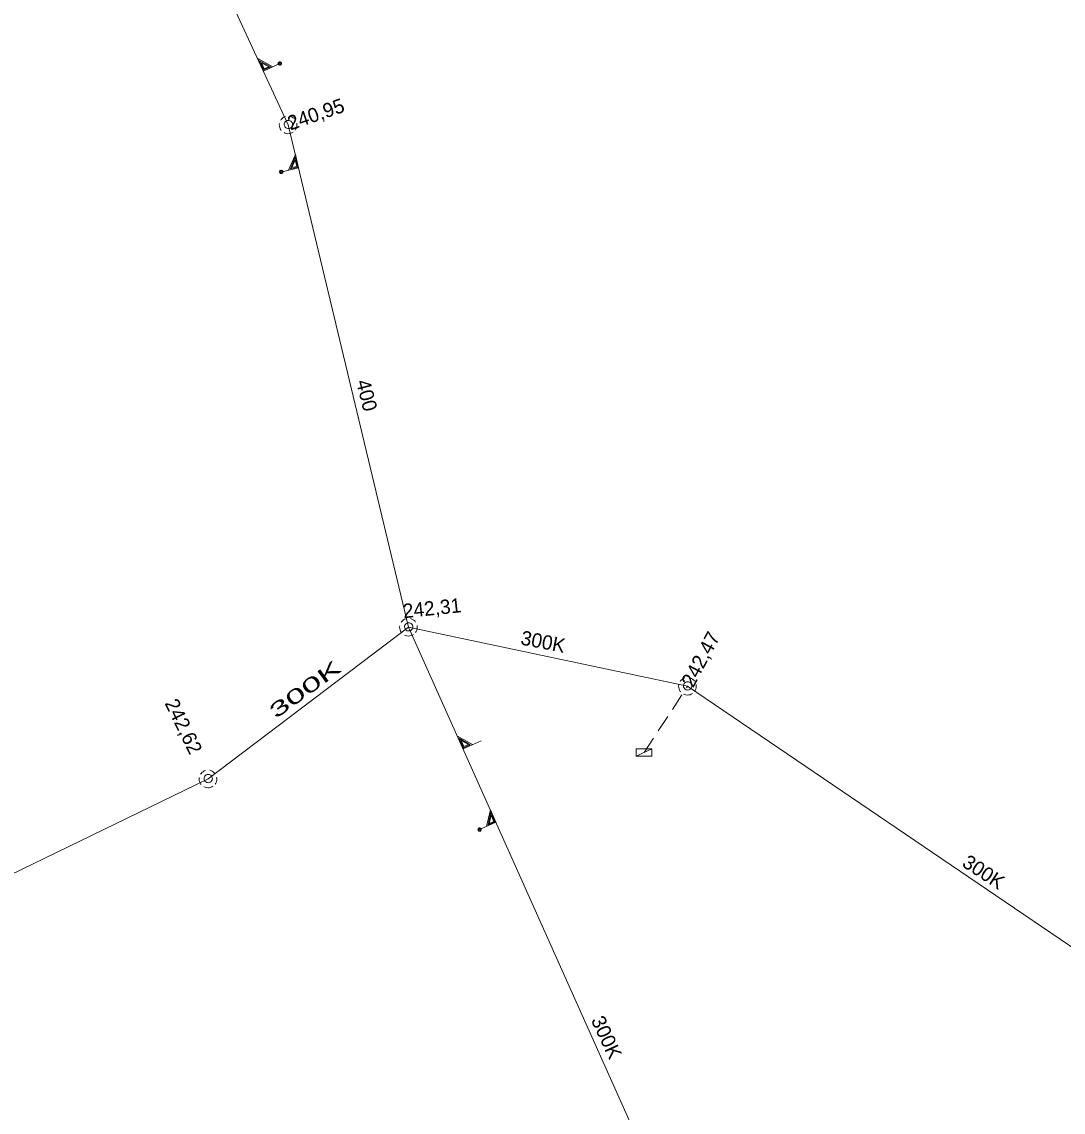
# Model space of a CAD drawing. Extents: x -735085 to -733500, y -1044153 to -1043402.
# Drawn here: x -734828.8 to -734770.5, y -1043658 to -1043597 of the extents above; entities that cross this region are included whole.
import ezdxf

# ---------------------------------------------------------------- set-up
doc = ezdxf.new("R2010")
doc.units = 0
doc.header["$LTSCALE"] = 0.32
doc.linetypes.add('MEDIUM_DASHED', pattern=[4.5, 3, -1.5])
doc.layers.add('16', color=7, linetype='Continuous')
for name, color, linetype, lineweight in [('18', 7, 'Continuous', 13), ('20', 7, 'Continuous', 13), ('49', 7, 'Continuous', 13)]:
    doc.layers.add(name, color=color, linetype=linetype, lineweight=lineweight)

msp = doc.modelspace()

# ---------------------------------------------------------------- linework, layer by layer
at = {"layer": '18'}
msp.add_line((-734794.411, -1043638.07), (-734793.537, -1043637.658), dxfattribs=at)
for points in [[(-734814.261, -1043599.314), (-734815.254, -1043599.776), (-734815.578, -1043599.077), (-734814.73, -1043599.532)], [(-734814.858, -1043599.536), (-734815.235, -1043599.712), (-734815.473, -1043599.198), (-734814.857, -1043599.536)], [(-734814.954, -1043599.529), (-734815.219, -1043599.652), (-734815.375, -1043599.315), (-734814.953, -1043599.53)], [(-734814.023, -1043602.307), (-734814.094, -1043602.335), (-734814.161, -1043602.374), (-734814.221, -1043602.422), (-734814.272, -1043602.479), (-734814.296, -1043602.513)], [(-734813.482, -1043602.49), (-734813.532, -1043602.432), (-734813.59, -1043602.382), (-734813.655, -1043602.341), (-734813.726, -1043602.312), (-734813.775, -1043602.298)], [(-734814.368, -1043602.699), (-734814.374, -1043602.776), (-734814.369, -1043602.853), (-734814.352, -1043602.928), (-734814.323, -1043602.999), (-734814.282, -1043603.065), (-734814.267, -1043603.087)], [(-734814.11, -1043603.216), (-734814.04, -1043603.247), (-734813.965, -1043603.266), (-734813.889, -1043603.273), (-734813.812, -1043603.268), (-734813.737, -1043603.251), (-734813.665, -1043603.223), (-734813.605, -1043603.188)], [(-734813.487, -1043603.076), (-734813.446, -1043603.011), (-734813.415, -1043602.941), (-734813.396, -1043602.866), (-734813.388, -1043602.79), (-734813.393, -1043602.713), (-734813.399, -1043602.678)], [(-734814.358, -1043605.434), (-734813.293, -1043605.179), (-734813.473, -1043604.429), (-734813.855, -1043605.314)], [(-734813.751, -1043605.236), (-734813.347, -1043605.139), (-734813.479, -1043604.589), (-734813.753, -1043605.237)], [(-734813.682, -1043605.171), (-734813.398, -1043605.103), (-734813.484, -1043604.742), (-734813.681, -1043605.172)], [(-734807.293, -1043630.387), (-734807.364, -1043630.415), (-734807.431, -1043630.454), (-734807.491, -1043630.502), (-734807.542, -1043630.559), (-734807.566, -1043630.593)], [(-734806.752, -1043630.57), (-734806.802, -1043630.512), (-734806.86, -1043630.462), (-734806.925, -1043630.421), (-734806.996, -1043630.392), (-734807.045, -1043630.378)], [(-734807.638, -1043630.779), (-734807.644, -1043630.856), (-734807.639, -1043630.933), (-734807.622, -1043631.008), (-734807.593, -1043631.079), (-734807.553, -1043631.145), (-734807.537, -1043631.167)], [(-734807.38, -1043631.296), (-734807.31, -1043631.327), (-734807.235, -1043631.346), (-734807.159, -1043631.353), (-734807.082, -1043631.348), (-734807.007, -1043631.331), (-734806.935, -1043631.303), (-734806.875, -1043631.268)], [(-734806.757, -1043631.156), (-734806.716, -1043631.091), (-734806.685, -1043631.021), (-734806.666, -1043630.946), (-734806.658, -1043630.87), (-734806.663, -1043630.793), (-734806.669, -1043630.758)], [(-734791.692, -1043633.687), (-734791.763, -1043633.715), (-734791.83, -1043633.754), (-734791.89, -1043633.802), (-734791.941, -1043633.859), (-734791.965, -1043633.893)], [(-734791.151, -1043633.87), (-734791.201, -1043633.812), (-734791.259, -1043633.762), (-734791.324, -1043633.721), (-734791.395, -1043633.692), (-734791.444, -1043633.678)], [(-734792.037, -1043634.079), (-734792.043, -1043634.156), (-734792.038, -1043634.233), (-734792.021, -1043634.308), (-734791.992, -1043634.379), (-734791.951, -1043634.445), (-734791.936, -1043634.467)], [(-734791.156, -1043634.456), (-734791.115, -1043634.391), (-734791.084, -1043634.321), (-734791.065, -1043634.246), (-734791.057, -1043634.17), (-734791.062, -1043634.093), (-734791.068, -1043634.058)], [(-734791.779, -1043634.596), (-734791.709, -1043634.627), (-734791.634, -1043634.646), (-734791.558, -1043634.653), (-734791.481, -1043634.648), (-734791.406, -1043634.631), (-734791.334, -1043634.603), (-734791.274, -1043634.568)], [(-734803.093, -1043637.211), (-734804.093, -1043637.659), (-734804.407, -1043636.956), (-734803.565, -1043637.423)], [(-734803.789, -1043637.417), (-734804.055, -1043637.535), (-734804.207, -1043637.196), (-734803.789, -1043637.418)], [(-734818.503, -1043638.867), (-734818.574, -1043638.895), (-734818.641, -1043638.934), (-734818.701, -1043638.982), (-734818.752, -1043639.039), (-734818.776, -1043639.073)], [(-734817.962, -1043639.05), (-734818.012, -1043638.992), (-734818.07, -1043638.942), (-734818.135, -1043638.901), (-734818.206, -1043638.872), (-734818.255, -1043638.858)], [(-734818.848, -1043639.259), (-734818.853, -1043639.336), (-734818.848, -1043639.413), (-734818.831, -1043639.488), (-734818.803, -1043639.559), (-734818.762, -1043639.625), (-734818.747, -1043639.647)], [(-734818.59, -1043639.776), (-734818.52, -1043639.807), (-734818.445, -1043639.826), (-734818.369, -1043639.833), (-734818.292, -1043639.828), (-734818.217, -1043639.811), (-734818.145, -1043639.783), (-734818.085, -1043639.748)], [(-734817.967, -1043639.636), (-734817.926, -1043639.571), (-734817.895, -1043639.501), (-734817.875, -1043639.426), (-734817.868, -1043639.35), (-734817.873, -1043639.273), (-734817.879, -1043639.238)], [(-734803.257, -1043642.212), (-734802.257, -1043641.765), (-734802.572, -1043641.061), (-734802.785, -1043642.001)], [(-734802.697, -1043641.906), (-734802.317, -1043641.736), (-734802.548, -1043641.22), (-734802.699, -1043641.907)], [(-734802.641, -1043641.829), (-734802.374, -1043641.71), (-734802.525, -1043641.371), (-734802.64, -1043641.83)]]:
    msp.add_lwpolyline(points, dxfattribs=at)
for points in [[(-734814.386, -1043599.269), (-734814.413, -1043599.288), (-734814.432, -1043599.316), (-734814.44, -1043599.348), (-734814.436, -1043599.381), (-734814.421, -1043599.411), (-734814.396, -1043599.434), (-734814.365, -1043599.447), (-734814.331, -1043599.448), (-734814.3, -1043599.436), (-734814.274, -1043599.416), (-734814.257, -1043599.387), (-734814.252, -1043599.353), (-734814.258, -1043599.321), (-734814.275, -1043599.291), (-734814.301, -1043599.27), (-734814.333, -1043599.261), (-734814.367, -1043599.262)], [(-734814.375, -1043599.294), (-734814.398, -1043599.311), (-734814.412, -1043599.335), (-734814.413, -1043599.363), (-734814.404, -1043599.39), (-734814.385, -1043599.411), (-734814.358, -1043599.42), (-734814.33, -1043599.419), (-734814.305, -1043599.407), (-734814.287, -1043599.385), (-734814.28, -1043599.358), (-734814.285, -1043599.33), (-734814.3, -1043599.306), (-734814.325, -1043599.291), (-734814.352, -1043599.287)], [(-734813.639, -1043602.759), (-734813.645, -1043602.707), (-734813.663, -1043602.657), (-734813.691, -1043602.613), (-734813.729, -1043602.576), (-734813.774, -1043602.549), (-734813.824, -1043602.533), (-734813.876, -1043602.528), (-734813.928, -1043602.535), (-734813.977, -1043602.554), (-734814.021, -1043602.584), (-734814.056, -1043602.623), (-734814.082, -1043602.668), (-734814.097, -1043602.719), (-734814.1, -1043602.771), (-734814.092, -1043602.823), (-734814.071, -1043602.871), (-734814.041, -1043602.914), (-734814.001, -1043602.949), (-734813.955, -1043602.973), (-734813.904, -1043602.987), (-734813.852, -1043602.989), (-734813.8, -1043602.979), (-734813.752, -1043602.957), (-734813.71, -1043602.925), (-734813.677, -1043602.885), (-734813.653, -1043602.838), (-734813.641, -1043602.787)], [(-734814.289, -1043605.32), (-734814.319, -1043605.333), (-734814.344, -1043605.357), (-734814.358, -1043605.387), (-734814.36, -1043605.42), (-734814.352, -1043605.452), (-734814.332, -1043605.479), (-734814.304, -1043605.498), (-734814.271, -1043605.506), (-734814.238, -1043605.502), (-734814.208, -1043605.486), (-734814.186, -1043605.461), (-734814.174, -1043605.43), (-734814.174, -1043605.396), (-734814.184, -1043605.365), (-734814.206, -1043605.339), (-734814.236, -1043605.322), (-734814.269, -1043605.317)], [(-734814.281, -1043605.346), (-734814.306, -1043605.358), (-734814.325, -1043605.38), (-734814.333, -1043605.406), (-734814.328, -1043605.435), (-734814.313, -1043605.458), (-734814.29, -1043605.474), (-734814.262, -1043605.479), (-734814.234, -1043605.471), (-734814.213, -1043605.453), (-734814.2, -1043605.428), (-734814.199, -1043605.399), (-734814.209, -1043605.374), (-734814.23, -1043605.354), (-734814.257, -1043605.344)], [(-734806.909, -1043630.839), (-734806.915, -1043630.787), (-734806.933, -1043630.737), (-734806.961, -1043630.693), (-734806.999, -1043630.656), (-734807.044, -1043630.629), (-734807.094, -1043630.613), (-734807.146, -1043630.608), (-734807.198, -1043630.615), (-734807.247, -1043630.634), (-734807.291, -1043630.664), (-734807.326, -1043630.703), (-734807.352, -1043630.748), (-734807.367, -1043630.799), (-734807.37, -1043630.851), (-734807.362, -1043630.903), (-734807.341, -1043630.951), (-734807.311, -1043630.994), (-734807.271, -1043631.029), (-734807.225, -1043631.053), (-734807.174, -1043631.067), (-734807.122, -1043631.069), (-734807.07, -1043631.059), (-734807.022, -1043631.037), (-734806.98, -1043631.005), (-734806.947, -1043630.965), (-734806.923, -1043630.918), (-734806.911, -1043630.867)], [(-734791.308, -1043634.139), (-734791.314, -1043634.087), (-734791.331, -1043634.037), (-734791.36, -1043633.993), (-734791.398, -1043633.956), (-734791.443, -1043633.929), (-734791.493, -1043633.913), (-734791.545, -1043633.908), (-734791.597, -1043633.915), (-734791.646, -1043633.934), (-734791.69, -1043633.964), (-734791.725, -1043634.003), (-734791.751, -1043634.048), (-734791.766, -1043634.099), (-734791.769, -1043634.151), (-734791.761, -1043634.203), (-734791.74, -1043634.251), (-734791.71, -1043634.294), (-734791.67, -1043634.329), (-734791.624, -1043634.353), (-734791.573, -1043634.367), (-734791.521, -1043634.369), (-734791.469, -1043634.359), (-734791.421, -1043634.337), (-734791.379, -1043634.305), (-734791.346, -1043634.265), (-734791.322, -1043634.218), (-734791.309, -1043634.167)], [(-734803.693, -1043637.425), (-734804.073, -1043637.595), (-734804.304, -1043637.078)], [(-734794.415, -1043637.658), (-734793.541, -1043637.658), (-734793.541, -1043638.07), (-734794.415, -1043638.07)], [(-734818.119, -1043639.319), (-734818.125, -1043639.267), (-734818.142, -1043639.217), (-734818.171, -1043639.173), (-734818.209, -1043639.136), (-734818.254, -1043639.109), (-734818.304, -1043639.093), (-734818.356, -1043639.088), (-734818.407, -1043639.095), (-734818.456, -1043639.114), (-734818.5, -1043639.144), (-734818.536, -1043639.183), (-734818.562, -1043639.228), (-734818.576, -1043639.279), (-734818.58, -1043639.331), (-734818.571, -1043639.383), (-734818.551, -1043639.431), (-734818.521, -1043639.474), (-734818.481, -1043639.509), (-734818.434, -1043639.533), (-734818.384, -1043639.547), (-734818.331, -1043639.549), (-734818.28, -1043639.539), (-734818.232, -1043639.517), (-734818.19, -1043639.485), (-734818.157, -1043639.445), (-734818.133, -1043639.398), (-734818.12, -1043639.347)], [(-734803.21, -1043642.087), (-734803.237, -1043642.106), (-734803.257, -1043642.134), (-734803.266, -1043642.166), (-734803.262, -1043642.199), (-734803.247, -1043642.229), (-734803.223, -1043642.252), (-734803.191, -1043642.265), (-734803.158, -1043642.267), (-734803.126, -1043642.257), (-734803.1, -1043642.235), (-734803.083, -1043642.207), (-734803.077, -1043642.174), (-734803.083, -1043642.141), (-734803.099, -1043642.112), (-734803.125, -1043642.091), (-734803.157, -1043642.08), (-734803.191, -1043642.081)], [(-734803.197, -1043642.111), (-734803.22, -1043642.128), (-734803.234, -1043642.153), (-734803.237, -1043642.181), (-734803.227, -1043642.208), (-734803.208, -1043642.228), (-734803.182, -1043642.239), (-734803.154, -1043642.239), (-734803.128, -1043642.226), (-734803.111, -1043642.204), (-734803.103, -1043642.177), (-734803.107, -1043642.149), (-734803.121, -1043642.126), (-734803.146, -1043642.11), (-734803.174, -1043642.105)]]:
    msp.add_lwpolyline(points, close=True, dxfattribs=at)
at = {"layer": '20'}
for p, q in [((-734813.87, -1043602.77), (-734827.03, -1043574.42)), ((-734813.87, -1043602.77), (-734827.03, -1043574.42)), ((-734818.35, -1043639.33), (-734807.14, -1043630.85)), ((-734818.35, -1043639.33), (-734807.14, -1043630.85)), ((-734843.64, -1043651.62), (-734818.35, -1043639.33)), ((-734843.64, -1043651.62), (-734818.35, -1043639.33))]:
    msp.add_line(p, q, dxfattribs=at)
for points in [[(-734791.539, -1043634.15), (-734807.14, -1043630.85), (-734813.87, -1043602.77)], [(-734791.539, -1043634.15), (-734807.14, -1043630.85), (-734813.87, -1043602.77)], [(-734771.699, -1043708.8), (-734785.92, -1043678.28), (-734807.14, -1043630.85)], [(-734771.699, -1043708.8), (-734785.92, -1043678.28), (-734807.14, -1043630.85)], [(-734716.17, -1043642.37), (-734757, -1043657.6), (-734791.539, -1043634.15)], [(-734716.17, -1043642.37), (-734757, -1043657.6), (-734791.539, -1043634.15)]]:
    msp.add_lwpolyline(points, dxfattribs=at)
at = {"layer": '49', "linetype": 'MEDIUM_DASHED'}
msp.add_line((-734793.969, -1043637.86), (-734791.539, -1043634.15), dxfattribs=at)
msp.add_line((-734793.969, -1043637.86), (-734791.539, -1043634.15), dxfattribs=at)

# ---------------------------------------------------------------- texts
at = {"layer": '16'}
for s, rotation, p in [('240,95', 19, (-734813.747, -1043603.093)), ('400 ', 284, (-734810.085, -1043617.127)), ('242,31', 6, (-734807.42, -1043630.361)), ('300K', 349, (-734800.921, -1043631.821)), ('242,47', 62, (-734791.229, -1043634.282)), ('242,62', 296, (-734820.802, -1043635.105)), ('300K', 327, (-734776.249, -1043644.192)), ('300K', 295, (-734796.962, -1043652.819))]:
    msp.add_text(s, height=0.8, rotation=rotation, dxfattribs=at).set_placement(p)
at = {"layer": '16', "width": 1.85}
msp.add_text('300K', height=0.8, rotation=36, dxfattribs=at).set_placement((-734814.572, -1043636.003))

doc.saveas('drawing.dxf')
